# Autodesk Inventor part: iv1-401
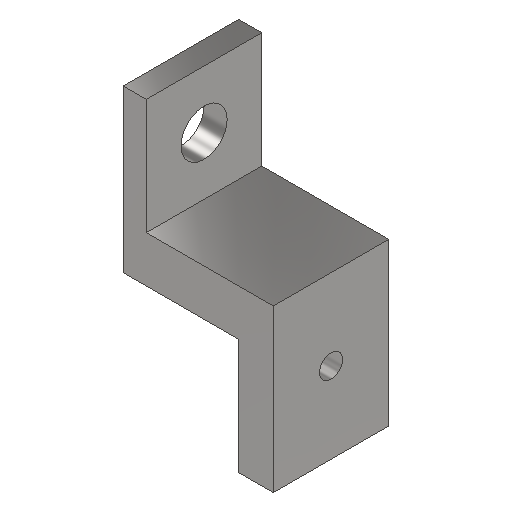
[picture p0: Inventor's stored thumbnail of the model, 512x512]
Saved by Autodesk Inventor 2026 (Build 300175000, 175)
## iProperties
Shininess: 64.0
Angle Display Precision: 2
Document Length Units: 11269
Document Angle Units: 11279
Document Time Units: 11290
Document Mass Units: 11283
Document Length Units Precision: 3
Document Angle Units Precision: 2
Created: 2002-04
Part Number: iv1-401
Document SubType Name: Modeling
Designer: Lars Bertram Pedersen
Material: Steel, Mild
Density: 7.85 g/cm^3
Appearance: Semi-Polished
Mass: 966.965 g
Surface Area: 239.142 cm^2
Volume: 123.18 cm^3
Density: 0.0
Volumn: 0.0
Area: 0.0
PropertySet Name: Model Information
Control State: 0
Master: False
Checked Out: False
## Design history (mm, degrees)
sketch "Sketch1"
  geometry: L1 (-50, 120)-(-40, 120); L2 (-40, 120)-(-40, 70); L3 (-40, 70)-(15, 70); L4 (15, 70)-(15, 0); L5 (15, 0)-(0, 0); L6 (0, 0)-(0, 50); L7 (0, 50)-(-50, 50); L8 (-50, 50)-(-50, 120); 1 further point
  constraints: 16 end point, 4 parallel, 3 perpendicular, 1 coincident, 1 horizontal
  dimensions: "d3" = 50 distance of L6.end L7.end; "d4" = 15 distance of L4.end L5.end; "d5" = 50 distance between parallel lines of L5 L7; "d8" = 50 distance of L1.end L2.end; "d9" = 10 distance of L1.start L1.end; "d10" = 20 distance between parallel lines of L7 L3
extrude "Extrusion1" new body sketch "Sketch1" distance "d11" = 50; taper "d12" = 0 deg
sketch "Sketch2"
  geometry: L1 (0, 50)-(0, 0) reference; L2 (0, 50)-(-50, 50) reference; C1 r 10 at (-25, 25)
  constraints: 1 centre point
  dimensions: "d13" = 20 diameter of C1; "d14" = 25 distance from line of L2 C1.centre; "d15" = 25 distance from line of L1 C1.centre
extrude "Extrusion2" cut sketch "Sketch2" extent not by distance; stored distance "d16" = 50; taper "d17" = 0 deg
sketch "Sketch4"
  geometry: L1 (-50, 70)-(-50, 0) reference; L2 (0, 0)-(-50, 0) reference; C1 r 5 at (-25, 35)
  constraints: 1 centre point
  dimensions: "d23" = 10 diameter of C1; "d24" = 25 distance from line of L1 C1.centre; "d25" = 35 distance from line of L2 C1.centre
extrude "Extrusion4" cut sketch "Sketch4" distance "d26" = 50; taper "d27" = 0 deg
body "Solid1"
